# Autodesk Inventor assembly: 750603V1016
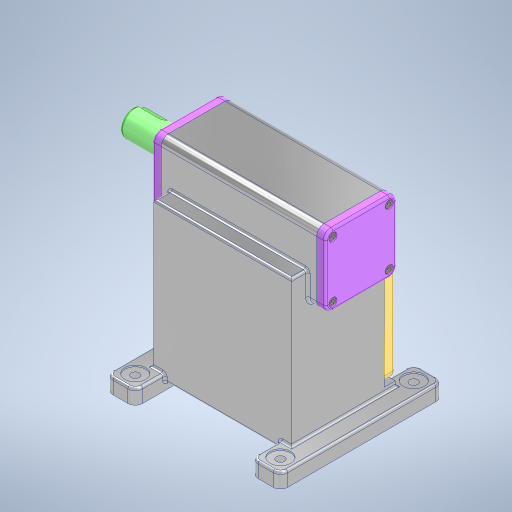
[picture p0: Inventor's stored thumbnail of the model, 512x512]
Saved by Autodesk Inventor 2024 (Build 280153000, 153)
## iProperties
Created: 2025-06
Part Number: 750603V1016
Document SubType Name: Assembly
Designer: 11
Author: 11
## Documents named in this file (13)
- C:\Users\11\Desktop\750603V1016\750603V1016.iam
- C:\Users\11\Desktop\750603V1016\750603V1016.ipt
- C:\Users\11\Desktop\750603V1016\깊은 홈 볼 베어링 6206\깊은 홈 볼 베어링 6206.ipt
- C:\Users\11\Desktop\750603V1016\깊은 홈 볼 베어링 6209\깊은 홈 볼 베어링 6209.ipt
- C:\Users\11\Desktop\750603V1016\뒷커버\뒷커버.ipt
- C:\Users\11\Desktop\750603V1016\앞커버\앞커버.ipt
- C:\Users\11\Desktop\750603V1016\오일 실 30 42 7\오일 실 30 42 7.ipt
- C:\Users\11\Desktop\750603V1016\오일 실 35 55 11\오일 실 35 55 11.ipt
- C:\Users\11\Desktop\750603V1016\웜 샤프트\웜 샤프트.ipt
- C:\Users\11\Desktop\750603V1016\웜 휠 커버\웜 휠 커버.ipt
- C:\Users\11\Desktop\750603V1016\웜 휠\웜 휠.ipt
- C:\Users\11\Desktop\750603V1016\6각 구멍붙이 볼트 M6x12\6각 구멍붙이 볼트 M6x12.ipt
- C:\Users\11\Desktop\750603V1016\6각 구멍붙이 볼트 M8x20\6각 구멍붙이 볼트 M8x20.ipt
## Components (13 placed, 3 different names)
1. 750603V1016:1
2. 6각 구멍붙이 볼트 M6x12:1
3. 6각 구멍붙이 볼트 M8x20:1
4. 6각 구멍붙이 볼트 M6x12:2
5. 6각 구멍붙이 볼트 M6x12:3
6. 6각 구멍붙이 볼트 M6x12:4
7. 6각 구멍붙이 볼트 M6x12:5
8. 6각 구멍붙이 볼트 M6x12:6
9. 6각 구멍붙이 볼트 M6x12:7
10. 6각 구멍붙이 볼트 M6x12:8
11. 6각 구멍붙이 볼트 M8x20:2
12. 6각 구멍붙이 볼트 M8x20:3
13. 6각 구멍붙이 볼트 M8x20:4
